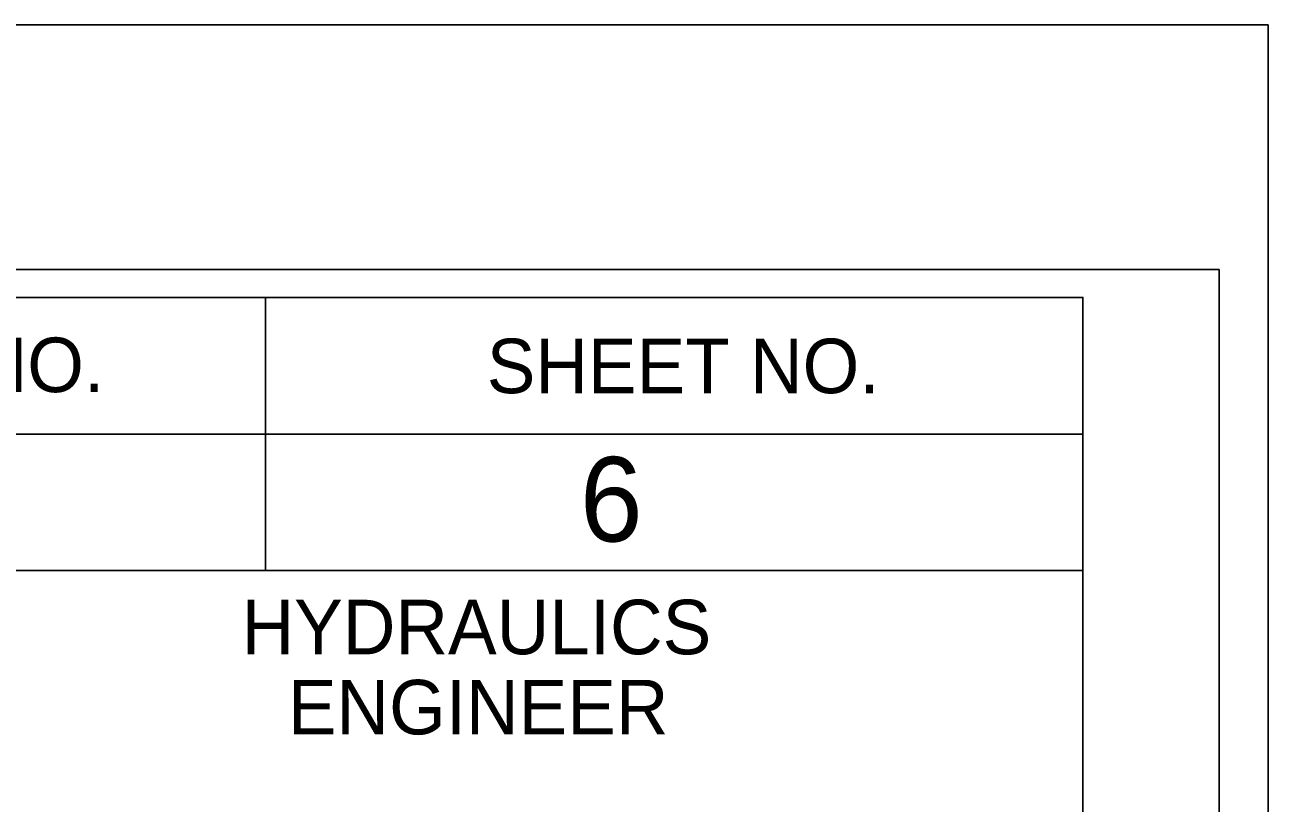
# Model space of a CAD drawing. Extents: x 1191114 to 1192543, y 893004 to 894332.
# Drawn here: x 1191793.56 to 1191839.19, y 894303.74 to 894332.3 of the extents above; entities that cross this region are included whole.
import ezdxf

# ---------------------------------------------------------------- set-up
doc = ezdxf.new("R2010")
doc.units = 0
for name, color, linetype in [('Sheet Cutting Line CELL', 7, 'Continuous'), ('Sheet Data Field CELL', 7, 'Continuous'), ('Sheet Plot Border Inside CELL', 7, 'Continuous'), ('Sheet Plot Border Outside CELL', 7, 'Continuous'), ('Sheet Profile CELL', 7, 'Continuous')]:
    doc.layers.add(name, color=color, linetype=linetype)

msp = doc.modelspace()

# ---------------------------------------------------------------- linework, layer by layer
at = {"layer": 'Sheet Cutting Line CELL'}
msp.add_line((1191839.186, 894332.299), (1191165.586, 894332.299), dxfattribs=at)
at = {"layer": 'Sheet Plot Border Inside CELL'}
msp.add_lwpolyline([(1191170.786, 893901.279), (1191837.386, 893901.279), (1191837.386, 894323.319), (1191170.786, 894323.319)], close=True, dxfattribs=at)
at = {"layer": 'Sheet Plot Border Outside CELL'}
msp.add_lwpolyline([(1191165.586, 893892.299), (1191839.186, 893892.299), (1191839.186, 894332.299), (1191165.586, 894332.299)], close=True, dxfattribs=at)
at = {"layer": 'Sheet Profile CELL'}
for p, q in [((1191802.386, 894322.279), (1191802.386, 894312.279)), ((1191752.366, 894317.279), (1191832.386, 894317.279))]:
    msp.add_line(p, q, dxfattribs=at)
for points in [[(1191832.386, 894322.299), (1191232.386, 894322.299), (1191232.386, 893902.299), (1191832.386, 893902.299)], [(1191752.366, 894322.299), (1191832.386, 894322.299), (1191832.386, 894312.279), (1191752.366, 894312.279)], [(1191792.386, 894312.279), (1191832.386, 894312.279), (1191832.386, 894267.279), (1191792.386, 894267.279)]]:
    msp.add_lwpolyline(points, close=True, dxfattribs=at)

# ---------------------------------------------------------------- texts
at = {"layer": 'Sheet Data Field CELL'}
msp.add_text('6  ', height=3.1, dxfattribs=at).set_placement((1191813.927, 894313.344))
at = {"layer": 'Sheet Profile CELL'}
for s, height, p in [('PROJECT REFERENCE NO.', 2.00004, (1191761.251, 894318.824)), ('SHEET NO.', 2, (1191810.511, 894318.784)), ('HYDRAULICS', 2, (1191801.511, 894309.204)), ('ENGINEER', 2, (1191803.211, 894306.264))]:
    msp.add_text(s, height=height, dxfattribs=at).set_placement(p)

doc.saveas('drawing.dxf')
